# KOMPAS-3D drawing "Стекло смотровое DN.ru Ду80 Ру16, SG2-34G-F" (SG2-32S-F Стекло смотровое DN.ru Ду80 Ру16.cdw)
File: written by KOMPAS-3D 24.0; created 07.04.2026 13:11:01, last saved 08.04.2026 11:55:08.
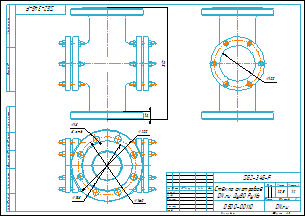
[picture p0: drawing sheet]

Document properties: Автор: Main; Форматы листов документа: A3; Полное имя файла: ..\SG2-34G-F Стекло смотровое DN.ru Ду80 Ру16\SG2-34G-F Стекло смотровое DN.ru Ду80 Ру16.m3d; Масса: 20.5; Наименование: Стекло смотровое DN.ru Ду80 Ру16; Количество листов документа: 1; Примечание: D500-00086

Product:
- Part/product: Стекло смотровое DN.ru Ду80 Ру16  | designation SG2-34G-F
    Масса: 20.5
    Раздел спецификации: Прочие изделия
    Примечание: D500-00086

Views: Вид 1, Снизу, Проекционный вид 2, Проекционный вид 3
Referenced files in D:\DN.ru Аутсерс\Стекло смотровое DN.ru\Стекло смотровое DN.ru SG2-34G-F тип В ГОСТ 21836-2021 Ду100 Ру16, углеродистая сталь, фланцевое\: SG2-34G-F тип В Стекло смотровое DN.ru Ду100 Ру16.m3d, SG2-34G-F тип ВСтекло смотровое DN.ru Ду100 Ру16.cdw
Referenced files in D:\DN.ru Аутсерс\Стекло смотровое DN.ru\SG2-34G-F Стекло смотровое DN.ru Ду80 Ру16\: SG2-34G-F Стекло смотровое DN.ru Ду80 Ру16.m3d
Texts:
  SG2-34G-F
  Стекло смотровое
  DN.ru Ду80 Ру16
  Стекло смотровое DN.ru Ду80 Ру16
  SG2-34G-F Стекло смотровое DN.ru Ду80 Ру16
Dimensions and other numbers on the sheet: 0; 3; 2; 4; 310; 20; 200; 138; 18; 8 отв.; 160; 100; 1:2; 1; 20,5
